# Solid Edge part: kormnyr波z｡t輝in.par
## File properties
Author: morva
Template: iso metric part.par
Last saved by: morva
Revision: 6
Application: Solid Edge
Density: 7833.000 kg/m^3
Accuracy: 0.990
Username: morva
Material: Steel
Face Style: Steel
Fill Style: ANSI32(Steel)
Virtual Style: Machined steel
Grouping: Metals\Steel
LibraryName: Materials
Coef. of Thermal Exp: 1.3e-05
Thermal Conductivity: 32.0
Specific Heat: 481.0
Modulus of Elasticity: 199947953000.0
Poisson's Ratio: 0.29
Yield Stress: 262000766.0
Ultimate Stress: 358527364.0
Elongation: 0.0
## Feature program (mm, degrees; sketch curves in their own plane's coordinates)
sketch for "unnamed Protrusion 1" plane through (0, 0, 0) normal (0, 0, 1) x-axis (1, 0, 0)
  circle centre (0, 0) radius 5
extrude "unnamed Protrusion 1" add finite 22 along +normal
sketch for "ExtrudedCutout_1" #1 plane through (0, 0, 0) normal (1, 0, 0) x-axis (0, 1, 0)
  circle centre (0, 11) radius 11
sketch for "ExtrudedCutout_1" #2 plane through (0, 0, 0) normal (1, 0, 0) x-axis (0, 1, 0)
  circle centre (0, 11) radius 15
extrude "ExtrudedCutout_1" cut finite 17.5177 symmetric
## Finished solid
Body 1: solid body, 3 faces, 2 edges, 0 vertices.
  Faces by surface: cylinder 3
  Edges by curve: intersection 2
Bounding box of the edges (mm): 10.000 x 9.999 x 22.000, from (-5, -4.9997, 0) to (4.9996, 4.9997, 22).
Cylindrical faces by radius (mm): R5 x1, R11 x2
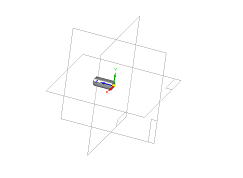
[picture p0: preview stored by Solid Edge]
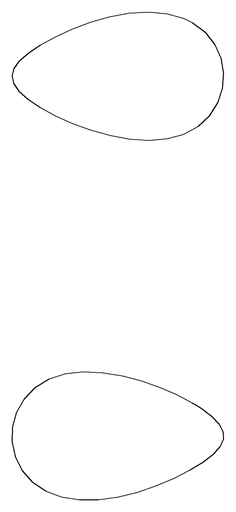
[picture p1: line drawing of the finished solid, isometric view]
